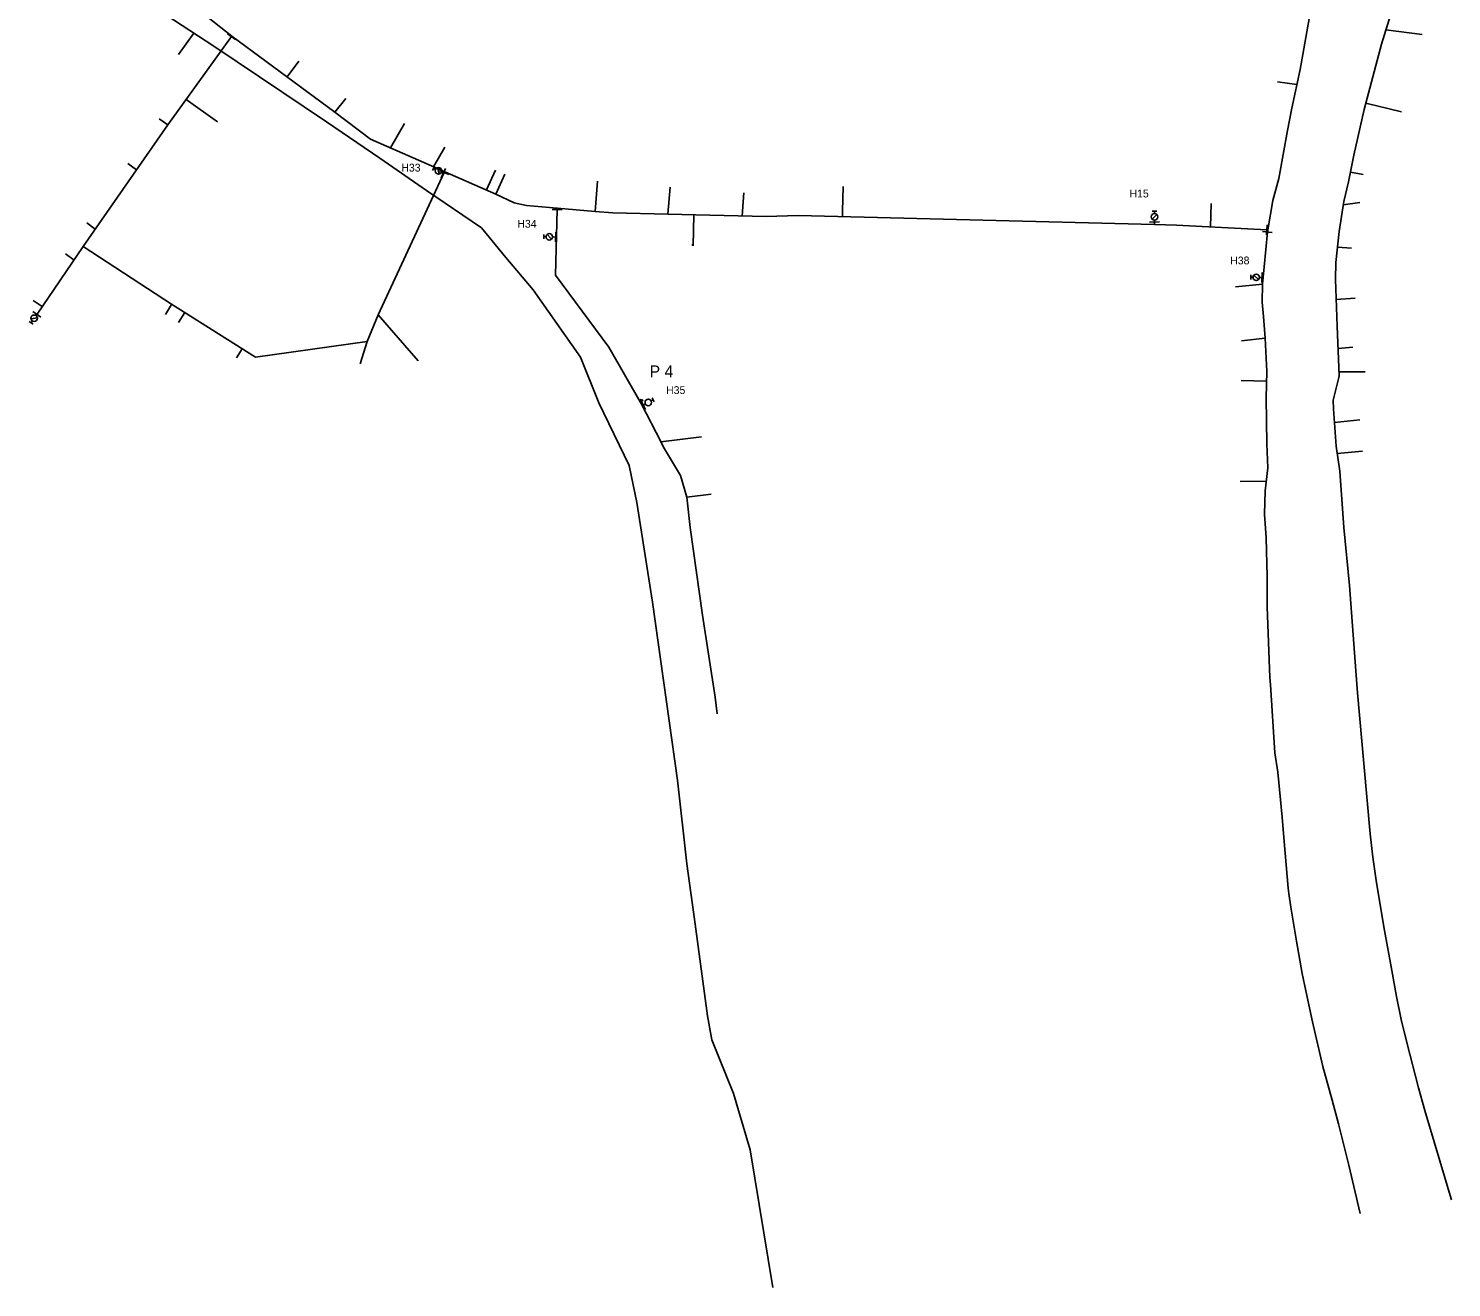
# Model space of a CAD drawing. Extents: x -548873 to -538270, y -1201997 to -1192514.
# Drawn here: x -547482.9 to -547118.9, y -1201562.1 to -1201240.2 of the extents above; entities that cross this region are included whole.
import ezdxf

# ---------------------------------------------------------------- set-up
doc = ezdxf.new("R2010")
doc.units = 0
for name, color, linetype in [('KN_HRAN_STÁTNÍ', 7, 'Continuous'), ('KN_PARC_Č', 7, 'Continuous'), ('KN_VKP_HRAN_SPORNÁ', 7, 'Continuous'), ('PK_PARC_Čv', 7, 'Continuous'), ('Vrstva 29', 7, 'Continuous'), ('Vrstva 39', 7, 'Continuous')]:
    doc.layers.add(name, color=color, linetype=linetype)

# ---------------------------------------------------------------- blocks, each defined once
blk = doc.blocks.new('160')
at = {"layer": 'KN_HRAN_STÁTNÍ'}
blk.add_circle((0, 0), 0.0458, dxfattribs=at)
blk = doc.blocks.new('147')
at = {"layer": 'KN_HRAN_STÁTNÍ'}
blk.add_line((0, 1.27), (0, -1.27), dxfattribs=at)
blk = doc.blocks.new('133')
at = {"layer": 'KN_HRAN_STÁTNÍ'}
for p, q in [((0.28, 0), (0, 0)), ((0.54, 0.58), (1.7, -0.58)), ((1.94, 0), (2.52, 0)), ((2.52, 0.58), (2.52, -0.58))]:
    blk.add_line(p, q, dxfattribs=at)
blk.add_circle((1.11, 0), 0.825, dxfattribs=at)
blk = doc.blocks.new('132')
at = {"layer": 'KN_HRAN_STÁTNÍ'}
for p, q in [((0.3, 0), (0, 0)), ((1.96, 0), (2.52, 0)), ((2.52, 0.58), (2.52, -0.58))]:
    blk.add_line(p, q, dxfattribs=at)
blk.add_circle((1.13, 0.01), 0.825, dxfattribs=at)
blk = doc.blocks.new('150')
at = {"layer": 'KN_HRAN_STÁTNÍ'}
blk.add_line((0, 1.27), (0, -1.27), dxfattribs=at)
blk = doc.blocks.new('128')
at = {"layer": 'KN_HRAN_STÁTNÍ'}
for p, q in [((-0.19, 1.06), (-0.43, 1.15)), ((-0.36, 0.84), (-0.19, 1.06)), ((-0.19, 1.06), (-0.02, 1.25)), ((-0.19, 1.06), (0, 0)), ((0.05, 0.95), (-0.19, 1.06)), ((-0.1, 1), (0.41, 0.91)), ((-0.07, 0.82), (0.17, 0.96)), ((0.17, 0.96), (-0.02, 1.13)), ((0.17, 0.96), (0, 0)), ((0.19, 1.21), (0.17, 0.96)), ((0.17, 0.96), (0.38, 1.08)), ((0.36, 0.77), (0.17, 0.96))]:
    blk.add_line(p, q, dxfattribs=at)

msp = doc.modelspace()

# ---------------------------------------------------------------- linework, layer by layer
at = {"layer": 'KN_PARC_Č'}
for points in [[(-547440.585, -1201241.32), (-547444.491, -1201246.826)], [(-547135.682, -1201240.542), (-547126.356, -1201241.697)], [(-547416.738, -1201252.528), (-547413.759, -1201248.486)], [(-547158.439, -1201254.441), (-547163.39, -1201253.8)], [(-547442.519, -1201258.281), (-547434.553, -1201264.017)], [(-547404.531, -1201261.525), (-547401.722, -1201258.024)], [(-547140.76, -1201259.219), (-547131.654, -1201261.513)], [(-547447.219, -1201264.803), (-547449.499, -1201263.232)], [(-547390.291, -1201270.719), (-547386.713, -1201264.494)], [(-547379.263, -1201275.513), (-547376.352, -1201270.484)], [(-547455.225, -1201276.273), (-547457.462, -1201274.714)], [(-547365.702, -1201281.456), (-547363.46, -1201276.365)], [(-547363.333, -1201282.489), (-547361.084, -1201277.412)], [(-547337.935, -1201286.945), (-547337.339, -1201279.216)], [(-547144.756, -1201276.908), (-547141.445, -1201277.477)], [(-547319.383, -1201287.672), (-547318.794, -1201280.731)], [(-547300.337, -1201288.075), (-547299.886, -1201282.213)], [(-547274.664, -1201288.287), (-547274.636, -1201286.908), (-547274.503, -1201280.585)], [(-547180.565, -1201290.89), (-547180.358, -1201284.907)], [(-547146.584, -1201285.227), (-547142.359, -1201284.649)], [(-547465.828, -1201291.461), (-547467.977, -1201289.874)], [(-547312.73, -1201287.813), (-547312.896, -1201295.713)], [(-547471.258, -1201299.322), (-547473.457, -1201297.8)], [(-547312.891, -1201295.463), (-547313.184, -1201295.454)], [(-547148.063, -1201296.12), (-547144.427, -1201296.314)], [(-547167.195, -1201305.506), (-547174.124, -1201306.249)], [(-547148.368, -1201309.488), (-547143.522, -1201309.096)], [(-547479.41, -1201311.286), (-547481.698, -1201309.698)], [(-547446.273, -1201310.7), (-547447.878, -1201313.305)], [(-547442.938, -1201312.797), (-547444.505, -1201315.379)], [(-547393.468, -1201313.413), (-547383.179, -1201325.129)], [(-547396.285, -1201320.201), (-547398.03, -1201325.886)], [(-547166.54, -1201319.31), (-547172.604, -1201319.993)], [(-547428.235, -1201322.042), (-547429.687, -1201324.404)], [(-547147.894, -1201321.967), (-547144.103, -1201321.67)], [(-547383.241, -1201325.059), (-547383.148, -1201324.986)], [(-547166.182, -1201330.363), (-547172.678, -1201330.177)], [(-547147.677, -1201327.941), (-547140.977, -1201327.941)], [(-547148.844, -1201340.941), (-547142.363, -1201340.269)], [(-547321.115, -1201345.837), (-547310.706, -1201344.606)], [(-547148.12, -1201348.828), (-547141.648, -1201348.257)], [(-547166.287, -1201355.887), (-547172.956, -1201356.026)], [(-547314.528, -1201359.983), (-547308.293, -1201359.229)]]:
    msp.add_lwpolyline(points, dxfattribs=at)
at = {"layer": 'KN_VKP_HRAN_SPORNÁ'}
for points in [[(-547447.389, -1201228.957), (-547430.869, -1201242.112)], [(-547118.878, -1201539.681), (-547119.5, -1201537.77), (-547125.72, -1201516.89), (-547127.31, -1201511.08), (-547130.28, -1201499.43), (-547131.78, -1201493.56), (-547132.96, -1201487.68), (-547134.15, -1201481.02), (-547136.16, -1201469.89), (-547138.15, -1201458), (-547138.97, -1201452.05), (-547139.67, -1201446.08), (-547141.29, -1201428.15), (-547142.91, -1201410.05), (-547143.36, -1201404.39), (-547144.98, -1201382.6), (-547146.47, -1201367.77), (-547147.45, -1201353.4), (-547148.39, -1201346.99), (-547149.11, -1201337.4), (-547149.19, -1201335.18), (-547147.72, -1201329.4), (-547147.64, -1201328.95), (-547148.1, -1201316.32), (-547148.57, -1201304.32), (-547148.47, -1201300.04), (-547147.64, -1201292.04), (-547146.45, -1201284.36), (-547145.25, -1201279.41), (-547143.9, -1201272.57), (-547141.2, -1201260.89), (-547136.81, -1201244.2), (-547133.05, -1201232.01)], [(-547449.986, -1201235.215), (-547435.21, -1201244.81), (-547406.63, -1201264.03), (-547392.99, -1201273.3), (-547381.08, -1201281.63), (-547367.01, -1201291.14), (-547360.83, -1201298.7), (-547353.81, -1201306.95), (-547341.67, -1201324.18), (-547336.99, -1201335.91), (-547329.24, -1201351.9), (-547327.295, -1201361.339), (-547323.293, -1201386.882), (-547316.891, -1201432.394), (-547314.523, -1201453.79), (-547312.399, -1201469.169), (-547309.22, -1201492.68), (-547308.13, -1201498.74), (-547302.55, -1201512.53), (-547298.32, -1201526.93), (-547292.491, -1201562.123)], [(-547165.902, -1201291.683), (-547164.61, -1201284.15), (-547163.06, -1201278.5), (-547160.86, -1201266.24), (-547159.74, -1201260.54), (-547157.63, -1201250.65), (-547154.96, -1201235.71)], [(-547468.93, -1201295.905), (-547447.23, -1201264.819), (-547430.96, -1201242.239)], [(-547430.96, -1201242.239), (-547430.869, -1201242.112)], [(-547430.869, -1201242.112), (-547404.531, -1201261.525), (-547395.448, -1201268.477), (-547379.037, -1201275.611), (-547376.434, -1201276.775)], [(-547376.523, -1201276.967), (-547376.434, -1201276.775)], [(-547376.434, -1201276.775), (-547363.314, -1201282.497), (-547358.661, -1201284.76), (-547355.481, -1201285.465), (-547347.676, -1201286.123)], [(-547468.93, -1201295.905), (-547446.326, -1201310.667), (-547424.81, -1201324.195), (-547396.285, -1201320.201), (-547393.471, -1201313.42), (-547376.523, -1201276.967)], [(-547347.677, -1201286.418), (-547348.109, -1201303.256), (-547334.443, -1201321.677), (-547326.078, -1201336.228)], [(-547347.676, -1201286.123), (-547347.677, -1201286.418)], [(-547347.676, -1201286.123), (-547337.941, -1201286.944), (-547333.4, -1201287.327), (-547319.391, -1201287.672), (-547294.178, -1201288.205), (-547286.013, -1201288.001), (-547194.854, -1201290.303), (-547189.197, -1201290.423), (-547166.149, -1201291.67)], [(-547142.29, -1201543.21), (-547145.12, -1201530.79), (-547147.77, -1201520.24), (-547149.45, -1201514.24), (-547151.77, -1201505.63), (-547154.45, -1201494.18), (-547156.19, -1201486.29), (-547157.06, -1201481.78), (-547158.57, -1201473.51), (-547159.95, -1201464.85), (-547160.471, -1201461.346), (-547160.67, -1201460.01), (-547161.72, -1201448.03), (-547162.2, -1201441.86), (-547163.34, -1201430.36), (-547164.06, -1201425.35), (-547165.21, -1201407.99), (-547165.32, -1201406.12), (-547166.07, -1201388.07), (-547166.05, -1201380.33), (-547166.33, -1201370.4), (-547166.69, -1201364.37), (-547166.57, -1201358.43), (-547165.91, -1201352.5), (-547166.11, -1201346.34), (-547166.27, -1201334.57), (-547166.13, -1201327.85), (-547166.54, -1201319.31), (-547166.98, -1201313.83), (-547167.332, -1201310.106), (-547167.195, -1201305.506), (-547165.991, -1201292.204)], [(-547166.149, -1201291.67), (-547165.902, -1201291.683)], [(-547165.991, -1201292.204), (-547165.902, -1201291.683)], [(-547480.707, -1201313.188), (-547468.93, -1201295.905)], [(-547326.078, -1201336.228), (-547321.072, -1201345.921), (-547320.455, -1201347.227), (-547316.07, -1201354.45), (-547314.52, -1201360.01), (-547313.645, -1201367.775), (-547310.509, -1201390.157), (-547307.248, -1201411.131), (-547306.71, -1201415.43)]]:
    msp.add_lwpolyline(points, dxfattribs=at)
at = {"layer": 'PK_PARC_Čv'}
for points in [[(-547376.639, -1201277.215), (-547376.964, -1201277.077)], [(-547194.827, -1201290.304), (-547194.83, -1201289.424)], [(-547347.859, -1201293.494), (-547348.562, -1201293.466)], [(-547167.044, -1201303.834), (-547167.72, -1201303.82)], [(-547480.707, -1201313.188), (-547480.81, -1201313.34)], [(-547325.898, -1201336.577), (-547325.354, -1201336.317)]]:
    msp.add_lwpolyline(points, dxfattribs=at)

# ---------------------------------------------------------------- block references
for name, p, xscale, yscale, rotation in [('133', (-547376.964, -1201277.077), 1.0225848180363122, 1.0225848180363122, 154.18102564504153), ('150', (-547376.801, -1201277.146), 1.0225848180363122, 1.0225848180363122, -25.81897435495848), ('133', (-547194.83, -1201289.424), 1.000000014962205, 1.0000000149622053, 90.99999994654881), ('150', (-547194.829, -1201289.664), 1.000000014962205, 1.0000000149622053, -89.0000000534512), ('133', (-547348.562, -1201293.466), 1.00000001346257, 1.0000000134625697, 178.0000000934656), ('150', (-547348.049, -1201293.487), 1.00000001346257, 1.0000000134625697, 178.0000000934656), ('133', (-547167.72, -1201303.82), 1.000000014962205, 1.0000000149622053, 179.0000000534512), ('150', (-547167.345, -1201303.828), 1.000000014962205, 1.0000000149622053, -0.9999999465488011), ('133', (-547480.81, -1201313.34), 0.9999999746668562, 0.999999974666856, -124.00000045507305), ('150', (-547480.76, -1201313.267), 0.9999999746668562, 0.999999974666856, 55.999999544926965), ('132', (-547325.354, -1201336.317), 1.0138865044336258, 1.0138865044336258, 27.56531359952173), ('150', (-547325.626, -1201336.447), 1.0138865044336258, 1.0138865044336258, 27.56531359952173)]:
    msp.add_blockref(name, p, dxfattribs=dict(at, xscale=xscale, yscale=yscale, rotation=rotation))
at = {"layer": 'Vrstva 29'}
for name, p, xscale, yscale, rotation in [('147', (-547430.96, -1201242.239), 1.000000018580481, 1.000000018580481, -125.00000023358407), ('160', (-547430.869, -1201242.112), 0.9999999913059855, 0.9999999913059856, 142.99999806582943), ('147', (-547376.523, -1201276.967), 0.9999999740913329, 0.9999999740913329, -114.00000060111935), ('160', (-547376.434, -1201276.775), 1.0225848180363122, 1.0225848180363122, -25.81897435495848), ('160', (-547347.676, -1201286.123), 1.0000000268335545, 1.0000000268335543, -3.9999997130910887), ('147', (-547166.149, -1201291.67), 1.0002788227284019, 1.0002788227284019, -3.2906995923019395), ('147', (-547165.991, -1201292.204), 1.000191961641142, 1.000191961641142, 82.91099886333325), ('160', (-547165.902, -1201291.683), 1.000000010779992, 1.0000000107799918, -51.00000108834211), ('160', (-547468.93, -1201295.905), 0.9999999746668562, 0.999999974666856, -124.00000045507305), ('160', (-547480.707, -1201313.188), 0.9999999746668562, 0.999999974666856, 55.999999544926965), ('160', (-547326.078, -1201336.228), 1.0000000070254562, 1.0000000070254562, 118.99999892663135)]:
    msp.add_blockref(name, p, dxfattribs=dict(at, xscale=xscale, yscale=yscale, rotation=rotation))
at = {"layer": 'Vrstva 29', "rotation": 90}
msp.add_blockref('147', (-547347.677, -1201286.418), dxfattribs=at)
at = {"layer": 'Vrstva 39'}
msp.add_blockref('128', (-547326.078, -1201336.228), dxfattribs=at)

# ---------------------------------------------------------------- texts
at = {"layer": 'PK_PARC_Čv'}
for s, height, p in [('H33', 2, (-547387.514, -1201276.747)), ('H15', 2, (-547201.25, -1201283.364)), ('H34', 2, (-547357.832, -1201291.096)), ('H38', 2, (-547175.48, -1201300.48)), ('P 4', 3, (-547323.984, -1201329.337)), ('H35', 2, (-547319.784, -1201333.637))]:
    msp.add_text(s, height=height, dxfattribs=at).set_placement(p)

doc.saveas('drawing.dxf')
